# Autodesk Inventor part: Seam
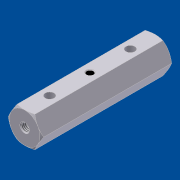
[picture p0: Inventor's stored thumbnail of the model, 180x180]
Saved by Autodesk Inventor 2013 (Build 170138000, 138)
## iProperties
Shininess: 50.0
Length Units: 11269
Angle Units: 11279
Time Units: 11290
Mass Units: 11283
Length Display Precision: 3
Angle Display Precision: 2
Created: 2001-04
Part Number: Seam
Material: Standard
Document SubType Name: Modellieren
Designer: dl
Density: 1 g/cm^3
Density: 0.0
Volumn: 0.0
Area: 0.0
PropertySet Name: Model Information
Control State: 0
Master: False
Checked Out: False
Author: dl
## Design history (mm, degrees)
body "Solid1"
sketch "Sketch3"
  geometry: A1 r 9.5 centre (10.97, 0) between (10.97, 9.5) and (2.742, 4.75) reference; 1 further point
  constraints: 1 coincident
sketch "Sketch4"
  geometry: L1 (10.97, -80.151)-(10.97, 0) reference; L2 (10.97, 0)-(0, 0) reference; L3 (5.485, 0)-(5.485, -81); 1 further point
  constraints: 2 end point, 1 midpoint, 1 parallel
  dimensions: "d29" = 40.5 distance from line of L2 point (5.485, -40.5) (= 0.5 x d6); "d30" = 0 distance from line of L3 point (5.485, -40.5)
sketch "Sketch5"
  geometry: L1 (0, 0)-(10.97, 0) reference; L2 (5.485, 81)-(5.485, 0); C1 r 2.067 at (5.485, 40.5) reference; 1 further point
  constraints: 2 end point, 1 midpoint
  dimensions: "d40" = 0 horizontal distance of L2.start point (5.485, 15.5); "d41" = 25 distance of C1.centre point (5.485, 15.5)
sketch "Sketch1"
  geometry: L1 (5.485, 9.5)-(16.454, 9.5); L2 (16.454, 9.5)-(21.939, 0); L3 (21.939, 0)-(16.454, -9.5); L4 (16.454, -9.5)-(5.485, -9.5); L5 (5.485, -9.5)-(0, 0); L6 (0, 0)-(5.485, 9.5)
  constraints: 12 end point, 3 parallel, 1 horizontal
  dimensions: "d0" = 19 distance from line of L4.end L1; "d1" = 19 distance between parallel lines of L5 L2 (= d0); "d2" = 19 distance between parallel lines of L3 L6 (= d0); "d3" = 120 deg angle of L6 L1; "d4" = 120 deg angle of L5 L6 (= d3); "d5" = 9.5 distance from line of L1 L5.end (= 0.5 x d0)
extrude "Extrusion1" new body sketch "Sketch1" distance "d6" = 81; taper "d7" = 0 deg
workplane "Work Plane1"
workplane "Work Plane2"
workaxis "Work Axis1"
revolve "Revolution1" stored, may be unused: angle "d17" = 90 deg
hole "Hole1" sketch "Sketch3" diameter "d18" = 4.917; stored, may be unused: countersink angle "d22" = 60 deg, drill point angle "d24" = 118 deg; dims "d19" = 9, "d20" = 4, "d21" = 2, "d23" = 11
chamfer "Chamfer1" distance "d27" = 0.5; stored, may be unused: second distance "d28" = 0.5, angle "d50" = 45 deg
hole "Hole2" sketch "Sketch4" diameter "d31" = 4.134; stored, may be unused: countersink angle "d35" = 60 deg, drill point angle "d37" = 118 deg; dims "d32" = 8, "d33" = 4, "d34" = 2, "d36" = 10
chamfer "Chamfer2" distance "d38" = 0.4; stored, may be unused: second distance "d39" = 0.4, angle "d51" = 45 deg
hole "Hole3" sketch "Sketch5" diameter "d42" = 5.5; stored, may be unused: countersink angle "d46" = 60 deg, drill point angle "d48" = 118 deg; dims "d43" = 8, "d44" = 10, "d45" = 5.7, "d47" = 10
workplane "Work Plane3"
mirror "Mirror1"
sketch "Sketch2"
  geometry: L1 (0, 0)-(10.97, 0) reference; L2 (5.485, 0)-(5.485, 74.44); L3 (0, 0)-(0, 81) reference; L4 (-4.015, 0)-(-9.015, 2.887); L5 (-9.015, 2.887)-(-9.015, 0); L6 (-9.015, 0)-(-4.015, 0); L7 (-5.485, 0)-(0, 0) reference; L8 (5.485, -24.3)-(5.485, 89.1) reference
  constraints: 8 end point, 1 horizontal, 1 midpoint, 1 parallel, 1 vertical
  dimensions: "d13" = 30 deg angle of L6 L4; "d14" = 0 distance between parallel lines of L7 L6; "d15" = 5 distance of L5.end L4.start; "d16" = 9.5 distance from line of L2 L4.start
other parameters: "d8" = -9.5 (= -0.5 x d0), "d10" = -9.5 (= -0.5 x d0), "d49" = -40.5 (= -0.5 x d6)
